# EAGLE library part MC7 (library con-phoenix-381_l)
Mini-Combicon 3.81mm horizontal 7-polig (ohne Gegenstecker)
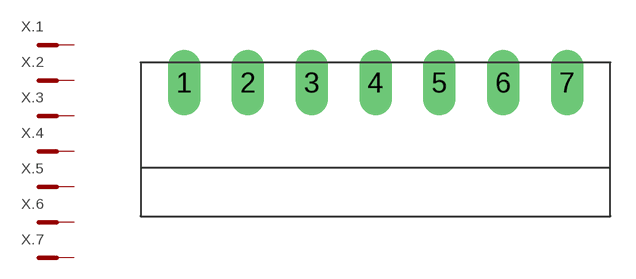
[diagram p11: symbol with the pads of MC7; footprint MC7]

Designator prefix X; gates .1=MCST .2=MCST .3=MCST .4=MCST .5=MCST .6=MCST .7=MCST

## MC7  [MC7]
1  .1:SK  pas
2  .2:SK  pas
3  .3:SK  pas
4  .4:SK  pas
5  .5:SK  pas
6  .6:SK  pas
7  .7:SK  pas

## Footprint MC7 (pad centres in mm)
Mini-Combicon 3.81mm horizontal 7-polig (ohne Gegenstecker)
drill 1.3 long: 1 -11.43,0; 2 -7.62,0; 3 -3.81,0; 4 0,0; 5 3.81,0; 6 7.62,0; 7 11.43,0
